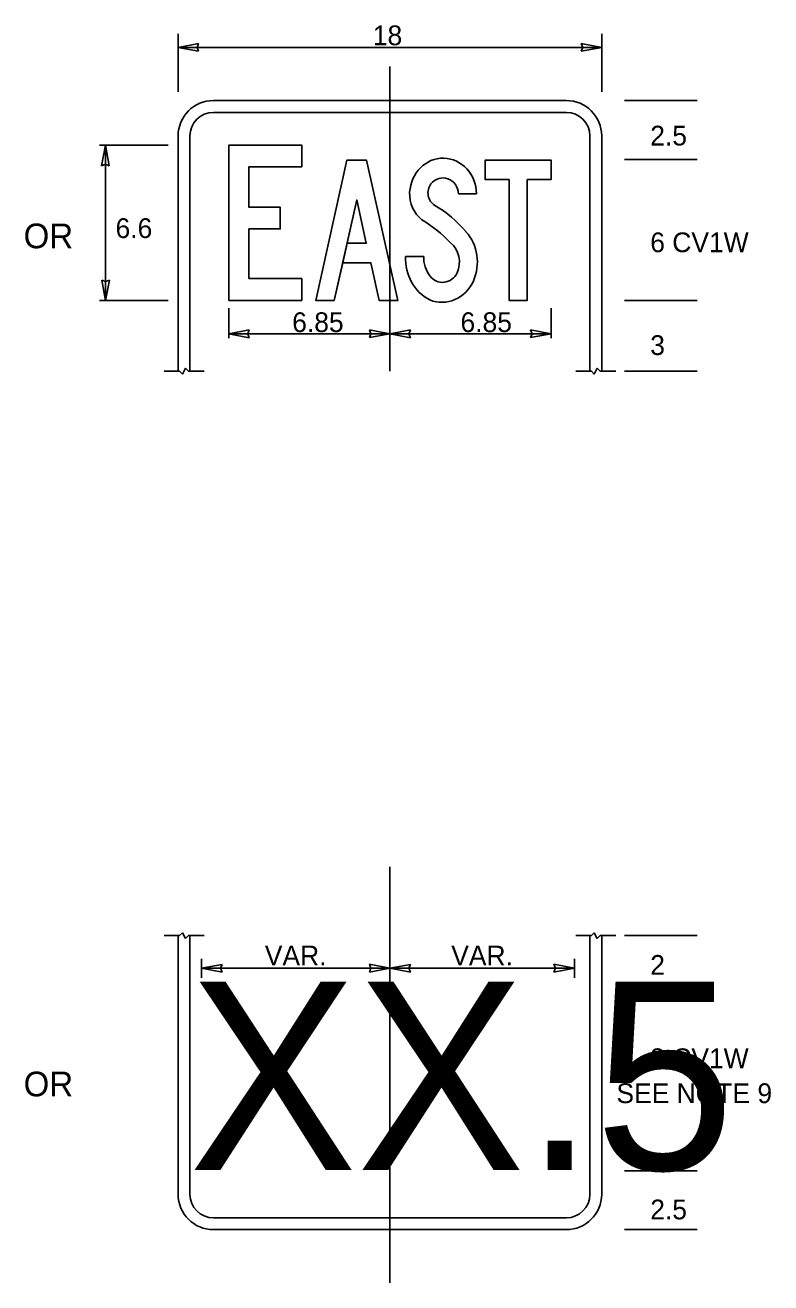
# Model space of a CAD drawing. Extents: x 56108 to 56734, y 11696 to 12110.
# Drawn here: x 56626.6 to 56732.3, y 11931.8 to 12110.1 of the extents above; entities that cross this region are included whole.
import ezdxf

# ---------------------------------------------------------------- set-up
doc = ezdxf.new("R2010")
doc.units = 0
for name, color, linetype in [('CL_dp', 7, 'Continuous'), ('GSDims', 7, 'Continuous'), ('SignPanel', 7, 'Continuous')]:
    doc.layers.add(name, color=color, linetype=linetype)

msp = doc.modelspace()

# ---------------------------------------------------------------- linework, layer by layer
at = {"layer": 'CL_dp'}
for p, q in [((56678.32, 12104.19), (56678.32, 12061.05)), ((56678.32, 11990.78), (56678.32, 11931.84))]:
    msp.add_line(p, q, dxfattribs=at)
at = {"layer": 'GSDims'}
for p, q in [((56648.32, 12100.62), (56648.32, 12108.84)), ((56708.32, 12100.62), (56708.32, 12108.84)), ((56651.22, 12107.46), (56648.32, 12106.92)), ((56708.32, 12106.92), (56648.32, 12106.92)), ((56648.32, 12106.92), (56651.22, 12106.36)), ((56651, 12106.92), (56651.22, 12107.46)), ((56651.22, 12106.36), (56651, 12106.92)), ((56708.32, 12106.92), (56705.42, 12107.48)), ((56705.42, 12107.48), (56705.64, 12106.92)), ((56705.64, 12106.92), (56705.42, 12106.38)), ((56705.42, 12106.38), (56708.32, 12106.92)), ((56721.86, 12099.38), (56711.57, 12099.38)), ((56646.9, 12093.05), (56637.16, 12093.05)), ((56638.03, 12093.05), (56637.47, 12090.15)), ((56638.03, 12093.05), (56638.03, 12071.05)), ((56638.57, 12090.15), (56638.03, 12093.05)), ((56721.86, 12091.05), (56711.57, 12091.05)), ((56637.47, 12090.15), (56638.03, 12090.37)), ((56638.03, 12090.37), (56638.57, 12090.15)), ((56638.03, 12073.73), (56637.49, 12073.95)), ((56637.49, 12073.95), (56638.03, 12071.05)), ((56638.03, 12071.05), (56638.59, 12073.95)), ((56638.59, 12073.95), (56638.03, 12073.73)), ((56646.9, 12071.05), (56637.16, 12071.05)), ((56655.49, 12069.96), (56655.49, 12065.71)), ((56701.15, 12069.96), (56701.15, 12065.71)), ((56721.86, 12071.05), (56711.57, 12071.05)), ((56658.39, 12066.87), (56655.49, 12066.33)), ((56655.49, 12066.33), (56678.32, 12066.33)), ((56655.49, 12066.33), (56658.39, 12065.77)), ((56658.17, 12066.33), (56658.39, 12066.87)), ((56658.39, 12065.77), (56658.17, 12066.33)), ((56678.32, 12066.33), (56675.42, 12066.89)), ((56675.42, 12066.89), (56675.64, 12066.33)), ((56675.64, 12066.33), (56675.42, 12065.79)), ((56675.42, 12065.79), (56678.32, 12066.33)), ((56681.22, 12066.87), (56678.32, 12066.33)), ((56678.32, 12066.33), (56701.15, 12066.33)), ((56678.32, 12066.33), (56681.22, 12065.77)), ((56681, 12066.33), (56681.22, 12066.87)), ((56681.22, 12065.77), (56681, 12066.33)), ((56701.15, 12066.33), (56698.25, 12066.89)), ((56698.25, 12066.89), (56698.47, 12066.33)), ((56698.47, 12066.33), (56698.25, 12065.79)), ((56698.25, 12065.79), (56701.15, 12066.33)), ((56721.86, 12061.05), (56711.57, 12061.05)), ((56721.86, 11981.05), (56711.57, 11981.05)), ((56651.64, 11977.77), (56651.64, 11975.08)), ((56654.54, 11976.96), (56651.64, 11976.42)), ((56654.32, 11976.42), (56654.54, 11976.96)), ((56678.32, 11976.42), (56675.42, 11976.98)), ((56675.42, 11976.98), (56675.64, 11976.42)), ((56681.22, 11976.96), (56678.32, 11976.42)), ((56681, 11976.42), (56681.22, 11976.96)), ((56704.45, 11976.42), (56701.55, 11976.98)), ((56701.55, 11976.98), (56701.77, 11976.42)), ((56704.45, 11977.77), (56704.45, 11975.08)), ((56651.64, 11976.42), (56678.32, 11976.42)), ((56651.64, 11976.42), (56654.54, 11975.86)), ((56654.54, 11975.86), (56654.32, 11976.42)), ((56675.64, 11976.42), (56675.42, 11975.88)), ((56675.42, 11975.88), (56678.32, 11976.42)), ((56678.32, 11976.42), (56681.22, 11975.86)), ((56678.32, 11976.42), (56704.45, 11976.42)), ((56681.22, 11975.86), (56681, 11976.42)), ((56701.77, 11976.42), (56701.55, 11975.88)), ((56701.55, 11975.88), (56704.45, 11976.42)), ((56721.86, 11974.38), (56711.57, 11974.38)), ((56721.86, 11947.71), (56711.57, 11947.71)), ((56721.86, 11939.38), (56711.57, 11939.38))]:
    msp.add_line(p, q, dxfattribs=at)
at = {"layer": 'SignPanel'}
for p, q in [((56688.05, 12086.17), (56690.6, 12086.17)), ((56688.05, 12086.17), (56690.6, 12086.17)), ((56688.05, 12086.17), (56690.6, 12086.17)), ((56683.11, 12077.3), (56680.53, 12077.3)), ((56683.11, 12077.3), (56680.53, 12077.3)), ((56683.11, 12077.3), (56680.53, 12077.3)), ((56646.32, 12061.05), (56648.53, 12061.05)), ((56648.53, 12061.05), (56648.95, 12060.63)), ((56649.36, 12061.46), (56648.95, 12060.63)), ((56649.36, 12061.46), (56649.77, 12061.05)), ((56649.77, 12061.05), (56651.99, 12061.05)), ((56704.65, 12061.05), (56706.87, 12061.05)), ((56706.87, 12061.05), (56707.28, 12060.63)), ((56707.69, 12061.46), (56707.28, 12060.63)), ((56707.69, 12061.46), (56708.1, 12061.05)), ((56708.1, 12061.05), (56710.32, 12061.05)), ((56646.32, 11981.05), (56648.53, 11981.05)), ((56648.53, 11981.05), (56648.95, 11981.46)), ((56649.36, 11980.63), (56648.95, 11981.46)), ((56649.36, 11980.63), (56649.77, 11981.05)), ((56649.77, 11981.05), (56651.99, 11981.05)), ((56704.65, 11981.05), (56706.87, 11981.05)), ((56706.87, 11981.05), (56707.28, 11981.46)), ((56707.69, 11980.63), (56707.28, 11981.46)), ((56707.69, 11980.63), (56708.1, 11981.05)), ((56708.1, 11981.05), (56710.32, 11981.05))]:
    msp.add_line(p, q, dxfattribs=at)
for points in [[(56653.32, 12099.38), (56703.32, 12099.38)], [(56653.32, 12097.71), (56703.32, 12097.71)], [(56648.32, 12061.05), (56648.32, 12094.38)], [(56649.99, 12061.05), (56649.99, 12094.38)], [(56706.65, 12094.38), (56706.65, 12061.05)], [(56708.32, 12094.38), (56708.32, 12061.05)], [(56648.32, 11944.38), (56648.32, 11981.05)], [(56649.99, 11944.38), (56649.99, 11981.05)], [(56706.65, 11981.05), (56706.65, 11944.38)], [(56708.32, 11981.05), (56708.32, 11944.38)], [(56703.32, 11941.05), (56653.32, 11941.05)], [(56703.32, 11939.38), (56653.32, 11939.38)]]:
    msp.add_lwpolyline(points, dxfattribs=at)
for points in [[(56658.34, 12074.14), (56658.34, 12081.19), (56662.78, 12081.19), (56662.78, 12084.27), (56658.34, 12084.27), (56658.34, 12089.99), (56665.83, 12089.99), (56665.83, 12093.08), (56655.51, 12093.08), (56655.51, 12071.06), (56665.83, 12071.06), (56665.83, 12074.14)], [(56658.34, 12074.14), (56658.34, 12081.19), (56662.78, 12081.19), (56662.78, 12084.27), (56658.34, 12084.27), (56658.34, 12089.99), (56665.83, 12089.99), (56665.83, 12093.08), (56655.51, 12093.08), (56655.51, 12071.06), (56665.83, 12071.06), (56665.83, 12074.14)], [(56658.34, 12074.14), (56658.34, 12081.19), (56662.78, 12081.19), (56662.78, 12084.27), (56658.34, 12084.27), (56658.34, 12089.99), (56665.83, 12089.99), (56665.83, 12093.08), (56655.51, 12093.08), (56655.51, 12071.06), (56665.83, 12071.06), (56665.83, 12074.14)], [(56675.6, 12076.39), (56676.79, 12071.06), (56679.42, 12071.06), (56674.99, 12090.95), (56672.24, 12090.95), (56667.81, 12071.06), (56670.44, 12071.06), (56671.63, 12076.39)], [(56672.25, 12079.17), (56671.63, 12076.39), (56675.6, 12076.39), (56676.79, 12071.06), (56679.42, 12071.06), (56674.99, 12090.95), (56672.24, 12090.95), (56667.81, 12071.06), (56670.44, 12071.06), (56673.62, 12085.29), (56674.98, 12079.17)], [(56672.25, 12079.17), (56671.63, 12076.39), (56675.6, 12076.39), (56676.79, 12071.06), (56679.42, 12071.06), (56674.99, 12090.95), (56672.24, 12090.95), (56667.81, 12071.06), (56670.44, 12071.06), (56673.62, 12085.29), (56674.98, 12079.17)], [(56695.21, 12088.17), (56691.83, 12088.17), (56691.83, 12090.95), (56701.15, 12090.95), (56701.15, 12088.17), (56697.77, 12088.17), (56697.77, 12071.06), (56695.21, 12071.06)], [(56695.21, 12088.17), (56691.83, 12088.17), (56691.83, 12090.95), (56701.15, 12090.95), (56701.15, 12088.17), (56697.77, 12088.17), (56697.77, 12071.06), (56695.21, 12071.06)], [(56695.21, 12088.17), (56691.83, 12088.17), (56691.83, 12090.95), (56701.15, 12090.95), (56701.15, 12088.17), (56697.77, 12088.17), (56697.77, 12071.06), (56695.21, 12071.06)], [(56673.62, 12085.29), (56674.98, 12079.17), (56672.25, 12079.17)]]:
    msp.add_lwpolyline(points, close=True, dxfattribs=at)
for centre, radius, start, end in [((56653.32, 12094.38), 5, 90, 180), ((56703.32, 12094.38), 5, 0, 90), ((56653.32, 12094.38), 3.33, 90, 180), ((56703.32, 12094.38), 3.33, 0, 90), ((56653.32, 11944.38), 5, 180, 270), ((56653.32, 11944.38), 3.33, 180, 270), ((56703.32, 11944.38), 5, 270, 360), ((56703.32, 11944.38), 3.33, 270, 360)]:
    msp.add_arc(centre, radius, start, end, dxfattribs=at)
for centre, major_axis, start_param, end_param in [((56685.85, 12086.05), (0, 5.16), 4.736267, 7.790596), ((56685.85, 12086.05), (0, 5.16), 4.736267, 7.790596), ((56685.85, 12086.05), (0, 5.16), 4.736267, 7.790596), ((56685.55, 12086.29), (0, 2), 0.87378, 2.656959), ((56685.55, 12086.29), (0, 2), 0.87378, 2.656959), ((56685.55, 12086.29), (0, 2), 0.87378, 2.656959), ((56685.83, 12085.99), (0, 2.43), 4.786904, 7.140738), ((56685.83, 12085.99), (0, 2.43), 4.786904, 7.140738), ((56685.83, 12085.99), (0, 2.43), 4.786904, 7.140738), ((56685.37, 12086.21), (0, 4.63), 1.534831, 2.511766), ((56685.37, 12086.21), (0, 4.63), 1.534831, 2.511766), ((56685.37, 12086.21), (0, 4.63), 1.534831, 2.511766), ((56676.27, 12067.78), (0, 19.09), 5.462886, 5.782242), ((56676.27, 12067.78), (0, 19.09), 5.462886, 5.782242), ((56676.27, 12067.78), (0, 19.09), 5.462886, 5.782242), ((56674.04, 12064.74), (0, 20.15), 5.515137, 5.786988), ((56674.04, 12064.74), (0, 20.15), 5.515137, 5.786988), ((56674.04, 12064.74), (0, 20.15), 5.515137, 5.786988), ((56685.04, 12076.49), (0, 6.17), 4.260987, 5.485755), ((56685.04, 12076.49), (0, 6.17), 4.260987, 5.485755), ((56685.04, 12076.49), (0, 6.17), 4.260987, 5.485755), ((56685, 12076.49), (0, 3.44), 4.254409, 5.632398), ((56685, 12076.49), (0, 3.44), 4.254409, 5.632398), ((56685, 12076.49), (0, 3.44), 4.254409, 5.632398), ((56686.5, 12077.01), (0, 6.5), 1.526364, 2.701682), ((56686.5, 12077.01), (0, 6.5), 1.526364, 2.701682), ((56686.5, 12077.01), (0, 6.5), 1.526364, 2.701682), ((56686.75, 12077.12), (0, 3.96), 1.524757, 2.28214), ((56686.75, 12077.12), (0, 3.96), 1.524757, 2.28214), ((56686.75, 12077.12), (0, 3.96), 1.524757, 2.28214), ((56685.78, 12076.14), (0, 2.53), 2.261787, 4.23006), ((56685.78, 12076.14), (0, 2.53), 2.261787, 4.23006), ((56685.78, 12076.14), (0, 2.53), 2.261787, 4.23006), ((56685.69, 12076.2), (0, 5.41), 2.786047, 4.251692), ((56685.69, 12076.2), (0, 5.41), 2.786047, 4.251692), ((56685.69, 12076.2), (0, 5.41), 2.786047, 4.251692)]:
    msp.add_ellipse(centre, major_axis=major_axis, ratio=0.91923, start_param=start_param, end_param=end_param, dxfattribs=at)

# ---------------------------------------------------------------- texts
at = {"layer": 'GSDims'}
for s, height, p in [('18', 2.8, (56675.9, 12107.22)), ('2.5', 2.8, (56715.2, 12093.01)), ('OR', 3.5, (56626.43, 12078.45)), ('6.6', 2.8, (56639.45, 12079.9)), ('6 CV1W', 2.8, (56715.2, 12077.89)), ('6.85', 2.8, (56664.48, 12066.57)), ('6.85', 2.8, (56688.32, 12066.57)), ('3', 2.8, (56715.2, 12063.32)), ('VAR.', 2.8, (56660.6, 11976.82)), ('VAR.', 2.8, (56687.01, 11976.82)), ('2', 2.8, (56715.2, 11975.49)), ('8 CV1W', 2.8, (56715.2, 11962.26)), ('OR', 3.5, (56626.43, 11958.27)), ('SEE NOTE 9', 2.8, (56710.41, 11957.31)), ('2.5', 2.8, (56715.2, 11940.84))]:
    msp.add_text(s, height=height, dxfattribs=at).set_placement(p)
at = {"layer": 'SignPanel'}
msp.add_text('XX.5', height=26.667, dxfattribs=at).set_placement((56649.85, 11947.85))

doc.saveas('drawing.dxf')
